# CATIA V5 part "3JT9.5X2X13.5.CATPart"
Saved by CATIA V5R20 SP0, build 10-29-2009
Part number: 3JT9.5X2X13.5
Revision: ANY
Definition: UNKNOWN
Nomenclature: 3JT9.5X2X13.5
Source: Unknown
Bounding box of the stored display mesh (mm): x -6.581 to 6.581, y -1 to 1, z -6.75 to 6.75
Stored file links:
  C:\Users\Utente\Desktop\IO LAVORO\3D X SITO CF\CUMSA\3D files PW\pw080825\pw080825_ejection\3JT9.5X2X13.5.CATPart
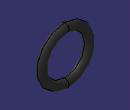
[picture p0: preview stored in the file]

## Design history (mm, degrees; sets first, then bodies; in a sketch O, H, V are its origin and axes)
Body1 "Revolución1" (main body)
  Solid1: solid without history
